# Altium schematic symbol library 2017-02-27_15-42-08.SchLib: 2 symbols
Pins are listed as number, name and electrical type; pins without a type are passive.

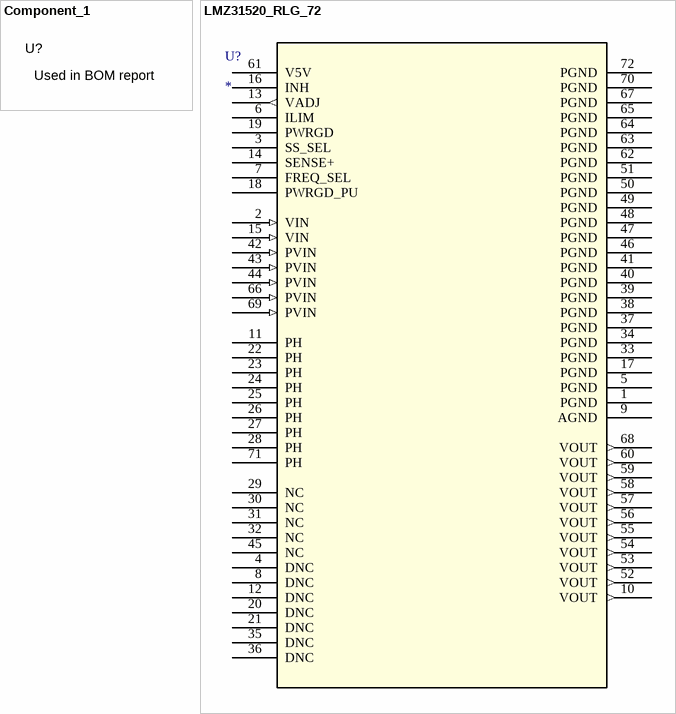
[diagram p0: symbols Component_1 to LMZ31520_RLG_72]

## Component_1
designator U?, comment Used in BOM report
SymbolVersion: use current date i.e. 2008-05-20; SymbolCreator: Use a-id; CompType: Used in some BOM reports.  Useful for finding later.; U/M: EA, IN, or GM

## LMZ31520_RLG_72
designator U?
Imported; Manufacturer_Part_Number: lmz31520_rlg_72; Vendor: Texas Instruments
footprint RLG72
pins: 1 PGND (power), 2 VIN (in), 3 SS_SEL, 4 DNC, 5 PGND (power), 6 ILIM, 7 FREQ_SEL, 8 DNC, 9 AGND (power), 10 VOUT (out), 11 PH, 12 DNC, 13 VADJ (out), 14 SENSE+, 15 VIN (in), 16 INH, 17 PGND (power), 18 PWRGD_PU (power), 19 PWRGD (power), 20 DNC, 21 DNC, 22 PH, 23 PH, 24 PH, 25 PH, 26 PH, 27 PH, 28 PH, 29 NC, 30 NC, 31 NC, 32 NC, 33 PGND (power), 34 PGND (power), 35 DNC, 36 DNC, 37 PGND (power), 38 PGND (power), 39 PGND (power), 40 PGND (power), 41 PGND (power), 42 PVIN (in), 43 PVIN (in), 44 PVIN (in), 45 NC, 46 PGND (power), 47 PGND (power), 48 PGND (power), 49 PGND (power), 50 PGND (power), 51 PGND (power), 52 VOUT (out), 53 VOUT (out), 54 VOUT (out), 55 VOUT (out), 56 VOUT (out), 57 VOUT (out), 58 VOUT (out), 59 VOUT (out), 60 VOUT (out), 61 V5V (power), 62 PGND (power), 63 PGND (power), 64 PGND (power), 65 PGND (power), 66 PVIN (in), 67 PGND (power), 68 VOUT (out), 69 PVIN (in), 70 PGND (power), 71 PH, 72 PGND (power)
